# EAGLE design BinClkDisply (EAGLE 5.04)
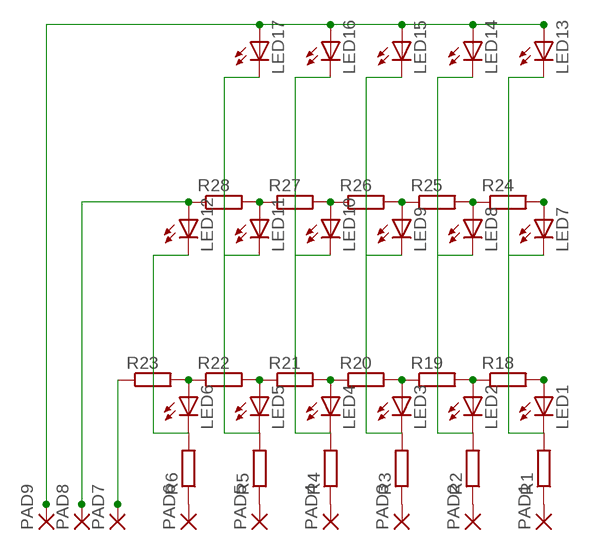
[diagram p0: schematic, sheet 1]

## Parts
LED1  LEDKA-3528ASYC  [KA-3528ASYC]
LED2  LEDKA-3528ASYC  [KA-3528ASYC]
LED3  LEDKA-3528ASYC  [KA-3528ASYC]
LED4  LEDKA-3528ASYC  [KA-3528ASYC]
LED5  LEDKA-3528ASYC  [KA-3528ASYC]
LED6  LEDKA-3528ASYC  [KA-3528ASYC]
LED7  LEDKA-3528ASYC  [KA-3528ASYC]
LED8  LEDKA-3528ASYC  [KA-3528ASYC]
LED9  LEDKA-3528ASYC  [KA-3528ASYC]
LED10  LEDKA-3528ASYC  [KA-3528ASYC]
LED11  LEDKA-3528ASYC  [KA-3528ASYC]
LED12  LEDKA-3528ASYC  [KA-3528ASYC]
LED13  LEDKA-3528ASYC  [KA-3528ASYC]
LED14  LEDKA-3528ASYC  [KA-3528ASYC]
LED15  LEDKA-3528ASYC  [KA-3528ASYC]
LED16  LEDKA-3528ASYC  [KA-3528ASYC]
LED17  LEDKA-3528ASYC  [KA-3528ASYC]
PAD1  SMD2  [SMD1,27-2,54]
PAD2  SMD2  [SMD1,27-2,54]
PAD3  SMD2  [SMD1,27-2,54]
PAD4  SMD2  [SMD1,27-2,54]
PAD5  SMD2  [SMD1,27-2,54]
PAD6  SMD2  [SMD1,27-2,54]
PAD7  SMD2  [SMD1,27-2,54]
PAD8  SMD2  [SMD1,27-2,54]
PAD9  SMD2  [SMD1,27-2,54]
R1  R-EU_M0805  [M0805]
R2  R-EU_M0805  [M0805]
R3  R-EU_M0805  [M0805]
R4  R-EU_M0805  [M0805]
R5  R-EU_M0805  [M0805]
R6  R-EU_M0805  [M0805]
R18  R-EU_M3516  [M3516]
R19  R-EU_M3516  [M3516]
R20  R-EU_M3516  [M3516]
R21  R-EU_M3516  [M3516]
R22  R-EU_M3516  [M3516]
R23  R-EU_M3516  [M3516]
R24  R-EU_M1406  [M1406]
R25  R-EU_M1406  [M1406]
R26  R-EU_M1406  [M1406]
R27  R-EU_M1406  [M1406]
R28  R-EU_M1406  [M1406]

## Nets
N$7: PAD1.1(P) R1.1
N$8: PAD2.1(P) R2.1
N$9: PAD3.1(P) R3.1
N$10: PAD4.1(P) R4.1
N$11: PAD5.1(P) R5.1
N$12: PAD6.1(P) R6.1
N$13: LED1.A R18.2
N$14: LED7.A R24.2
N$18: LED13.A LED14.A LED15.A LED16.A LED17.A PAD9.1(P)
N$24: LED2.A R18.1 R19.2
N$25: LED3.A R19.1 R20.2
N$26: LED4.A R20.1 R21.2
N$27: LED5.A R21.1 R22.2
N$28: LED6.A R22.1 R23.2
N$30: LED12.A PAD8.1(P) R28.1
N$31: LED1.C LED7.C LED13.C R1.2
N$32: LED2.C LED8.C LED14.C R2.2
N$33: LED3.C LED9.C LED15.C R3.2
N$34: LED4.C LED10.C LED16.C R4.2
N$35: LED5.C LED11.C LED17.C R5.2
N$36: LED6.C LED12.C R6.2
N$37: PAD7.1(P) R23.1
N$38: LED8.A R24.1 R25.2
N$39: LED9.A R25.1 R26.2
N$40: LED10.A R26.1 R27.2
N$41: LED11.A R27.1 R28.2

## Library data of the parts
LED1-LED17 = led:LED: LED
PAD1-PAD9 = wirepad:SMD2: SMD PAD
R1-R6 R18-R28 = rcl:R-EU_: RESISTOR, European symbol

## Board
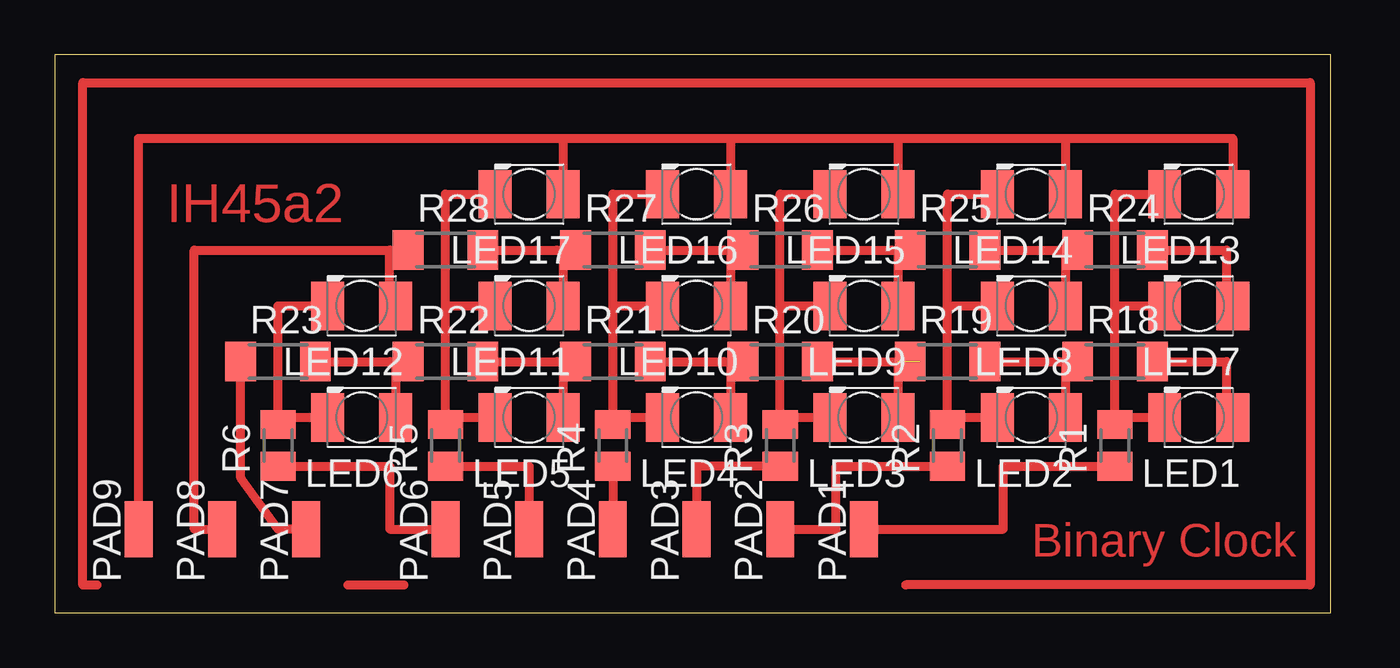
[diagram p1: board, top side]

Size 58.09 x 25.39 mm. Coordinates in mm from the lower left corner, seen from the top.
Outline: 0,0 58.09,0 58.09,25.39 0,25.39 0,0
Copper layers (1*16): Top 0.035mm / dielectric 1.5mm / Bottom 0.035mm
Design rules "default": minimum track width 10mil, minimum drill 24mil, track to track 8mil, track to pad 8mil, pad to pad 8mil, via to via 8mil, smd to smd 8mil, copper to edge 40mil, drill to drill 8mil, minimum pad ring 10mil, minimum via ring 8mil, stop-mask expansion 4mil, vias tented up to drill 0mil, thermal gap 10mil

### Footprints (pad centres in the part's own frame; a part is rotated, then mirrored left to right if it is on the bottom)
KA-3528ASYC = smd 1.5 x 2.2: A -1.55,0; C 1.55,0
SMD1,27-2,54 = smd 1.27 x 2.54: 1 0,0
M0805 = smd 1.3 x 1.6: 1 -0.95,0; 2 0.95,0
M3516 = smd 1.4 x 1.8: 1 -1.7,0; 2 1.7,0
M1406 = smd 1.4 x 1.8: 1 -1.7,0; 2 1.7,0

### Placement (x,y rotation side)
LED1  52.07,8.89 180 top
LED2  44.45,8.89 180 top
LED3  36.83,8.89 180 top
LED4  29.21,8.89 180 top
LED5  21.59,8.89 180 top
LED6  13.97,8.89 180 top
LED7  52.07,13.97 180 top
LED8  44.45,13.97 180 top
LED9  36.83,13.97 180 top
LED10  29.21,13.97 180 top
LED11  21.59,13.97 180 top
LED12  13.97,13.97 180 top
LED13  52.07,19.05 180 top
LED14  44.45,19.05 180 top
LED15  36.83,19.05 180 top
LED16  29.21,19.05 180 top
LED17  21.59,19.05 180 top
PAD1  36.83,3.81 0 top
PAD2  33.02,3.81 0 top
PAD3  29.21,3.81 0 top
PAD4  25.4,3.81 0 top
PAD5  21.59,3.81 0 top
PAD6  17.78,3.81 0 top
PAD7  11.43,3.81 0 top
PAD8  7.62,3.81 0 top
PAD9  3.81,3.81 0 top
R1  48.26,7.62 90 top
R2  40.64,7.62 90 top
R3  33.02,7.62 90 top
R4  25.4,7.62 90 top
R5  17.78,7.62 90 top
R6  10.16,7.62 90 top
R18  48.26,11.43 0 top
R19  40.64,11.43 0 top
R20  33.02,11.43 0 top
R21  25.4,11.43 0 top
R22  17.78,11.43 0 top
R23  10.16,11.43 0 top
R24  48.26,16.51 0 top
R25  40.64,16.51 0 top
R26  33.02,16.51 0 top
R27  25.4,16.51 0 top
R28  17.78,16.51 0 top

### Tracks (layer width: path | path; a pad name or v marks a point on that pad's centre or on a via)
N$1
  Top 0.406: 1.27,1.27 1.9,1.27
N$2
  Top 0.406: 57.15,1.27 38.73,1.27
N$3
  Top 0.406: 13.34,1.27 15.88,1.27
N$7
  Top 0.406: PAD1.1 43.18,3.81 43.18,6.67 R1.1 47.94,6.35
N$8
  Top 0.406: 40.64,6.35 R2.1 35.56,6.67 35.56,3.81 PAD2.1
N$9
  Top 0.406: R3.1 29.21,6.67 PAD3.1
N$10
  Top 0.406: R4.1 PAD4.1
N$11
  Top 0.406: R5.1 21.59,6.67 PAD5.1
N$12
  Top 0.406: R6.1 15.24,6.67 15.24,3.81 PAD6.1
N$13
  Top 0.406: R18.2 53.34,11.43 53.34,8.89 LED1.A
N$14
  Top 0.406: R24.2 53.34,16.51 53.34,13.97 LED7.A
N$18
  Top 0.406: PAD9.1 3.81,21.59 23.14,21.59 | 23.14,21.59 LED17.A | 30.48,19.05 LED16.A 30.76,21.59 30.48,21.59 | 38.1,19.05 LED15.A 38.38,21.59 38.1,21.59 | 45.72,19.05 LED14.A 46,21.59 45.72,21.59 | 53.34,19.05 LED13.A 53.62,21.59 45.72,21.59 | 23.14,21.59 30.48,21.59 | 30.48,21.59 38.1,21.59 | 38.1,21.59 45.72,21.59
N$24
  Top 0.406: R19.2 45.72,11.43 | 45.72,11.43 R18.1 | LED2.A 46,11.43 45.72,11.43
N$25  (1 unrouted)
  Top 0.406: LED3.A 38.38,11.43 R20.2 | R19.1 39.37,11.43
N$26
  Top 0.406: R21.2 30.48,11.43 | 30.48,11.43 R20.1 | LED4.A 30.76,11.43 30.48,11.43
N$27
  Top 0.406: R22.2 22.86,11.43 | 22.86,11.43 R21.1 | LED5.A 23.14,11.43 22.86,11.43
N$28
  Top 0.406: R23.2 15.24,11.43 | 15.24,11.43 R22.1 | LED6.A 15.52,11.43 15.24,11.43
N$30
  Top 0.406: PAD8.1 6.35,3.81 6.35,16.51 R28.1 15.24,16.51 15.24,13.97 LED12.A
N$31
  Top 0.406: 48.26,8.89 LED1.C | LED13.C 48.26,19.05 48.26,13.97 | 48.26,13.97 LED7.C | 48.26,8.89 48.26,13.97 | R1.2 48.26,8.89
N$32
  Top 0.406: LED2.C 40.64,8.89 R2.2 40.64,13.97 | LED14.C 40.64,19.05 40.64,13.97 | 40.64,13.97 LED8.C
N$33
  Top 0.406: LED3.C 33.02,8.89 R3.2 33.02,13.97 | LED15.C 33.02,19.05 33.02,13.97 | 33.02,13.97 LED9.C
N$34
  Top 0.406: LED4.C 25.4,8.89 R4.2 25.4,13.97 | LED16.C 25.4,19.05 25.4,13.97 | 25.4,13.97 LED10.C
N$35
  Top 0.406: 17.78,8.89 LED5.C | LED17.C 17.78,19.05 17.78,13.97 | 17.78,13.97 LED11.C | 17.78,8.89 17.78,13.97 | R5.2 17.78,8.89
N$36
  Top 0.406: LED6.C 10.16,8.89 R6.2 10.16,13.97 LED12.C
N$37
  Top 0.406: PAD7.1 10.16,3.81 8.46,6.15 R23.1
N$38
  Top 0.406: R25.2 45.72,16.51 | 45.72,16.51 R24.1 | LED8.A 46,16.51 45.72,16.51
N$39
  Top 0.406: R26.2 38.1,16.51 | 38.1,16.51 R25.1 | LED9.A 38.38,16.51 38.1,16.51
N$40
  Top 0.406: R27.2 30.48,16.51 | 30.48,16.51 R26.1 | LED10.A 30.76,16.51 30.48,16.51
N$41
  Top 0.406: R28.2 22.86,16.51 | 22.86,16.51 R27.1 | LED11.A 23.14,16.51 22.86,16.51
N$51
  Top 0.406: 57.15,1.27 57.15,24.13 1.27,24.13 1.27,1.27

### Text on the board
Top: IH45a2 | Binary Clock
